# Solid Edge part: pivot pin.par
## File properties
Author: Deepak Maini
Template: Normal.par
Last saved by: Robert a Rhodes jr
Revision: 5
Application: Solid Edge
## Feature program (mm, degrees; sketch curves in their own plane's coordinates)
sketch for "unnamed Protrusion 1" #1 plane through (0, 0, 0) normal (0, -1, 0) x-axis (1, 0, 0)
  circle centre (0, 0) radius 6
sketch for "unnamed Protrusion 1" #2 plane through (0, 0, 0) normal (0, -1, 0) x-axis (1, 0, 0)
  circle centre (0, 0) radius 7
extrude "unnamed Protrusion 1" add finite 106 symmetric
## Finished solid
Body 1: solid body, 4 faces, 4 edges, 0 vertices.
  Faces by surface: cylinder 2, plane 2
  Edges by curve: circle 4
Bounding box of the edges (mm): 14.000 x 106.000 x 14.000, from (-7, -53, -7) to (7, 53, 7).
Cylindrical faces by radius (mm): R6 x1, R7 x1
Planar faces by outward normal: +y 1, -y 1
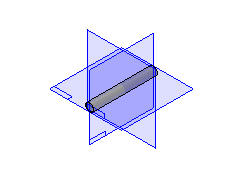
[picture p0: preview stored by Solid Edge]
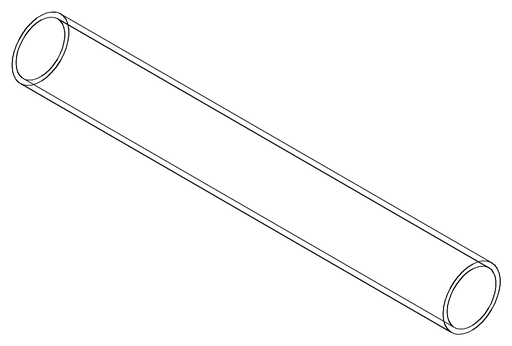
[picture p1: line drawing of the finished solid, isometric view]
